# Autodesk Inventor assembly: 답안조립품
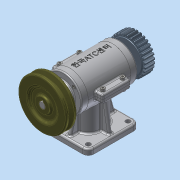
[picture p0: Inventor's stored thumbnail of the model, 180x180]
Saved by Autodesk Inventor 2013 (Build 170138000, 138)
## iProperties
Created: 2415-07
Part Number: 답안조립품
Document SubType Name: Assembly
Designer: Administrator
Author: Administrator
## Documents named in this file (19)
- C:\Users\Administrator\Desktop\350706V1010\답안조립품.iam
- C:\Users\Administrator\Desktop\350706V1010\본체.ipt
- C:\Users\Administrator\Desktop\350706V1010\M 4너트.ipt
- C:\Users\Administrator\Desktop\350706V1010\M3x0.5x8.ipt
- C:\Users\Administrator\Desktop\350706V1010\M4x20.ipt
- C:\Users\Administrator\Desktop\350706V1010\V-벨트풀리.ipt
- C:\Users\Administrator\Desktop\350706V1010\뒤커버.ipt
- C:\Users\Administrator\Desktop\350706V1010\멈춤나사.ipt
- C:\Users\Administrator\Desktop\350706V1010\메인기어.ipt
- C:\Users\Administrator\Desktop\350706V1010\베어링 6201.ipt
- C:\Users\Administrator\Desktop\350706V1010\베어링 6202.ipt
- C:\Users\Administrator\Desktop\350706V1010\본체 커버.ipt
- C:\Users\Administrator\Desktop\350706V1010\스프링-[가변].ipt
- C:\Users\Administrator\Desktop\350706V1010\슬라이드.ipt
- C:\Users\Administrator\Desktop\350706V1010\앞커버.ipt
- C:\Users\Administrator\Desktop\350706V1010\오일실.ipt
- C:\Users\Administrator\Desktop\350706V1010\키4x4.ipt
- C:\Users\Administrator\Desktop\350706V1010\키5x5.ipt
- C:\Users\Administrator\Desktop\350706V1010\편심축.ipt
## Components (17 placed, 4 different names)
1. V-벨트풀리:1 — 각도:5
2. M4x0.5x14:1 — 각도:1
3. M4x0.5x14:2
4. M4x0.5x14:3
5. M4x0.5x14:4
6. KS B 1012 모따기 안된 - 미터 B  M 4:1 — 각도:8
7. KS B 1012 모따기 안된 - 미터 B  M 4:2
8. KS B 1012 모따기 안된 - 미터 B  M 4:3
9. KS B 1012 모따기 안된 - 미터 B  M 4:4
10. M3x0.5x8:1 — 각도:2
11. M3x0.5x8:3
12. M3x0.5x8:4
13. M3x0.5x8:5
14. M3x0.5x8:2 — 각도:3
15. M3x0.5x8:6
16. M3x0.5x8:7
17. M3x0.5x8:8
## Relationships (5: Angle 5)
- 각도:1 [Angle]: M4x0.5x14:1
- 각도:2 [Angle]: M3x0.5x8:1
- 각도:3 [Angle]: M3x0.5x8:2
- 각도:5 [Angle]: V-벨트풀리:1
- 각도:8 [Angle]: KS B 1012 모따기 안된 - 미터 B  M 4:1
